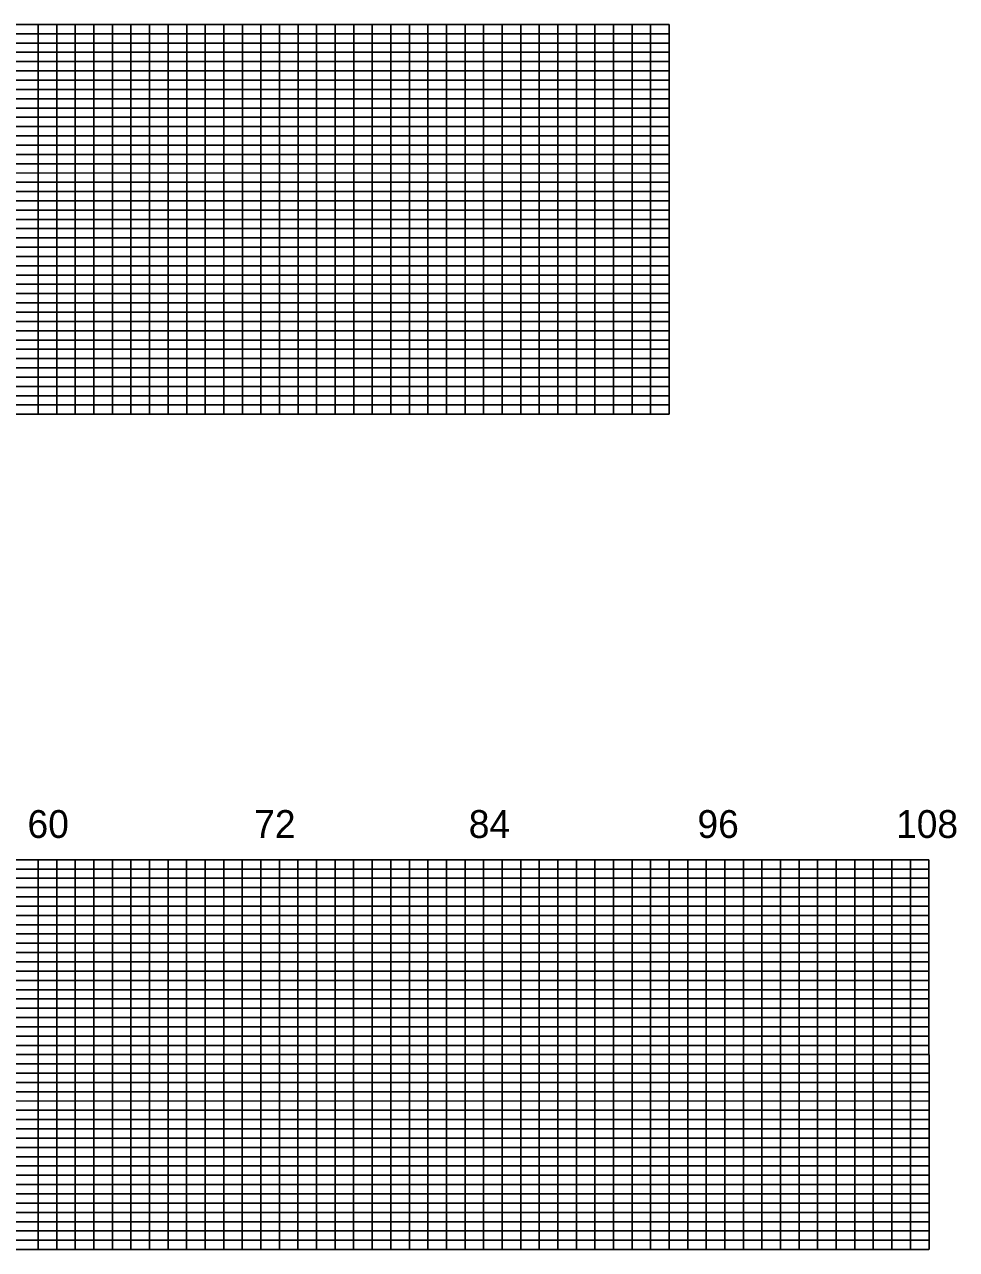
# Model space of a CAD drawing. Extents: x 1894907 to 1905782, y 740939 to 777025.
# Drawn here: x 1898545 to 1901056, y 765964 to 769264 of the extents above; entities that cross this region are included whole.
import ezdxf

# ---------------------------------------------------------------- set-up
doc = ezdxf.new("R2010")
doc.units = 0
doc.layers.add('RD_PD_WallFill', color=7, linetype='Continuous')

msp = doc.modelspace()

# ---------------------------------------------------------------- linework, layer by layer
at = {"layer": 'RD_PD_WallFill'}
for p, q in [((1894931.6, 769264.2), (1900281.6, 769264.2)), ((1895381.6, 769239.2), (1900281.6, 769239.2)), ((1898581.7, 768214.2), (1898581.7, 769264.2)), ((1898631.7, 768214.2), (1898631.7, 769264.2)), ((1898681.7, 768214.2), (1898681.7, 769264.2)), ((1898731.7, 768214.2), (1898731.7, 769264.2)), ((1898781.7, 768214.2), (1898781.7, 769264.2)), ((1898831.7, 768214.2), (1898831.7, 769264.2)), ((1898881.7, 768214.2), (1898881.7, 769264.2)), ((1898931.7, 768214.2), (1898931.7, 769264.2)), ((1898981.7, 768214.2), (1898981.7, 769264.2)), ((1899031.7, 768214.2), (1899031.7, 769264.2)), ((1899081.7, 768214.2), (1899081.7, 769264.2)), ((1899131.7, 768214.2), (1899131.7, 769264.2)), ((1899181.7, 768214.2), (1899181.7, 769264.2)), ((1899231.7, 768214.2), (1899231.7, 769264.2)), ((1899281.7, 768214.2), (1899281.7, 769264.2)), ((1899331.7, 768214.2), (1899331.7, 769264.2)), ((1899381.7, 768214.2), (1899381.7, 769264.2)), ((1899431.7, 768214.2), (1899431.7, 769264.2)), ((1899481.7, 768214.2), (1899481.7, 769264.2)), ((1899531.7, 768214.2), (1899531.7, 769264.2)), ((1899581.7, 768214.2), (1899581.7, 769264.2)), ((1899631.7, 768214.2), (1899631.7, 769264.2)), ((1899681.7, 768214.2), (1899681.7, 769264.2)), ((1899731.7, 768214.2), (1899731.7, 769264.2)), ((1899781.7, 768214.2), (1899781.7, 769264.2)), ((1899831.7, 768214.2), (1899831.7, 769264.2)), ((1899881.7, 768214.2), (1899881.7, 769264.2)), ((1899931.7, 768214.2), (1899931.7, 769264.2)), ((1899981.7, 768214.2), (1899981.7, 769264.2)), ((1900031.7, 768214.2), (1900031.7, 769264.2)), ((1900081.7, 768214.2), (1900081.7, 769264.2)), ((1900131.7, 768214.2), (1900131.7, 769264.2)), ((1900181.7, 768214.2), (1900181.7, 769264.2)), ((1900231.7, 768214.2), (1900231.7, 769264.2)), ((1900281.7, 768214.2), (1900281.7, 769264.2)), ((1895381.6, 769214.2), (1900281.6, 769214.2)), ((1895381.6, 769189.2), (1900281.6, 769189.2)), ((1895381.6, 769164.2), (1900281.6, 769164.2)), ((1895381.6, 769139.1), (1900281.6, 769139.2)), ((1894931.6, 769114.2), (1900281.6, 769114.2)), ((1894931.6, 769089.2), (1900281.6, 769089.1)), ((1894931.6, 769064.2), (1900281.6, 769064.2)), ((1894931.6, 769039.2), (1900281.6, 769039.1)), ((1894931.6, 769014.2), (1900281.6, 769014.2)), ((1894931.6, 768989.1), (1900281.6, 768989.2)), ((1894931.6, 768964.1), (1900281.6, 768964.2)), ((1894931.6, 768939.2), (1900281.6, 768939.1)), ((1894931.6, 768914.1), (1900281.6, 768914.2)), ((1894931.6, 768889.2), (1900281.6, 768889.2)), ((1894931.6, 768864.2), (1900281.6, 768864.1)), ((1894931.6, 768839.2), (1900281.6, 768839.2)), ((1894931.6, 768814.2), (1900281.6, 768814.1)), ((1894931.6, 768789.2), (1900281.6, 768789.2)), ((1894931.6, 768764.2), (1900281.6, 768764.2)), ((1894931.6, 768739.2), (1900281.6, 768739.1)), ((1894931.6, 768714.2), (1900281.6, 768714.2)), ((1894931.6, 768689.1), (1900281.6, 768689.2)), ((1894931.6, 768664.2), (1900281.6, 768664.2)), ((1894931.6, 768639.2), (1900281.6, 768639.2)), ((1894931.6, 768614.1), (1900281.6, 768614.2)), ((1894931.6, 768589.2), (1900281.6, 768589.1)), ((1894931.6, 768564.2), (1900281.6, 768564.2)), ((1894931.6, 768539.2), (1900281.6, 768539.2)), ((1894931.6, 768514.2), (1900281.6, 768514.1)), ((1894931.6, 768489.2), (1900281.6, 768489.2)), ((1894931.6, 768464.2), (1900281.6, 768464.2)), ((1894931.6, 768439.2), (1900281.6, 768439.2)), ((1894931.6, 768414.2), (1900281.6, 768414.2)), ((1894931.6, 768389.1), (1900281.6, 768389.2)), ((1894931.6, 768364.2), (1900281.6, 768364.1)), ((1894931.6, 768339.2), (1900281.6, 768339.2)), ((1894931.6, 768314.2), (1900281.6, 768314.2)), ((1894931.6, 768289.2), (1900281.6, 768289.2)), ((1894931.6, 768264.2), (1900281.6, 768264.2)), ((1894931.6, 768214.2), (1900281.6, 768214.1)), ((1894981.6, 768239.1), (1900281.6, 768239.2)), ((1895631.6, 767014.1), (1900981.6, 767014.2)), ((1898581.6, 765964.2), (1898581.6, 767014.2)), ((1898631.6, 765964.2), (1898631.6, 767014.2)), ((1898681.6, 765964.2), (1898681.6, 767014.2)), ((1898731.6, 765964.1), (1898731.6, 767014.2)), ((1898781.6, 765964.2), (1898781.6, 767014.2)), ((1898831.6, 765964.2), (1898831.6, 767014.2)), ((1898881.6, 765964.2), (1898881.6, 767014.2)), ((1898931.6, 765964.2), (1898931.6, 767014.2)), ((1898981.6, 765964.2), (1898981.6, 767014.2)), ((1899031.6, 765964.1), (1899031.6, 767014.2)), ((1899081.6, 765964.1), (1899081.6, 767014.2)), ((1899131.6, 765964.2), (1899131.6, 767014.2)), ((1899181.6, 765964.2), (1899181.6, 767014.2)), ((1899231.6, 765964.2), (1899231.6, 767014.2)), ((1899281.6, 765964.2), (1899281.6, 767014.2)), ((1899331.6, 765964.2), (1899331.6, 767014.2)), ((1899381.6, 765964.2), (1899381.6, 767014.2)), ((1899431.6, 765964.2), (1899431.6, 767014.2)), ((1899481.6, 765964.2), (1899481.6, 767014.2)), ((1899531.6, 765964.2), (1899531.6, 767014.2)), ((1899581.6, 765964.2), (1899581.6, 767014.2)), ((1899631.6, 765964.2), (1899631.6, 767014.2)), ((1899681.6, 765964.2), (1899681.6, 767014.2)), ((1899731.6, 765964.2), (1899731.6, 767014.2)), ((1899781.6, 765964.2), (1899781.6, 767014.2)), ((1899831.6, 765964.2), (1899831.6, 767014.2)), ((1899881.6, 765964.2), (1899881.6, 767014.2)), ((1899931.6, 765964.2), (1899931.6, 767014.2)), ((1899981.6, 765964.2), (1899981.6, 767014.2)), ((1900031.6, 765964.2), (1900031.6, 767014.2)), ((1900081.6, 765964.2), (1900081.6, 767014.2)), ((1900131.6, 765964.2), (1900131.6, 767014.2)), ((1900181.6, 765964.2), (1900181.6, 767014.2)), ((1900231.6, 765964.2), (1900231.6, 767014.2)), ((1900281.6, 765964.2), (1900281.6, 767014.2)), ((1900331.6, 765964.2), (1900331.6, 767014.2)), ((1900381.6, 765964.2), (1900381.6, 767014.2)), ((1900431.6, 765964.2), (1900431.6, 767014.2)), ((1900481.6, 765964.2), (1900481.6, 767014.2)), ((1900531.6, 765964.2), (1900531.6, 767014.2)), ((1900581.6, 765964.2), (1900581.6, 767014.2)), ((1900631.6, 765964.2), (1900631.6, 767014.2)), ((1900681.6, 765964.2), (1900681.6, 767014.2)), ((1900731.6, 765964.2), (1900731.6, 767014.2)), ((1900781.7, 765964.2), (1900781.6, 767014.2)), ((1900831.6, 765964.2), (1900831.7, 767014.2)), ((1900881.6, 765964.2), (1900881.6, 767014.2)), ((1900931.6, 765964.2), (1900931.6, 767014.2)), ((1900981.7, 765964.2), (1900981.6, 767014.2)), ((1896081.6, 766989.1), (1900981.6, 766989.1)), ((1896081.6, 766964.1), (1900981.6, 766964.1)), ((1896081.6, 766939.1), (1900981.6, 766939.1)), ((1896081.6, 766914.2), (1900981.6, 766914.1)), ((1895631.6, 766864.1), (1900981.6, 766864.1)), ((1896081.6, 766889.1), (1900981.6, 766889.2)), ((1895631.6, 766839.1), (1900981.6, 766839.1)), ((1895631.6, 766814.1), (1900981.6, 766814.2)), ((1895631.6, 766789.2), (1900981.6, 766789.1)), ((1895631.6, 766764.2), (1900981.6, 766764.2)), ((1895631.6, 766739.1), (1900981.6, 766739.1)), ((1895631.6, 766714.1), (1900981.6, 766714.1)), ((1895631.6, 766689.2), (1900981.6, 766689.1)), ((1895631.6, 766664.1), (1900981.6, 766664.1)), ((1895631.6, 766639.2), (1900981.6, 766639.1)), ((1895631.6, 766614.1), (1900981.6, 766614.1)), ((1895631.6, 766589.1), (1900981.6, 766589.2)), ((1895631.6, 766564.1), (1900981.6, 766564.1)), ((1895631.6, 766539.1), (1900981.6, 766539.2)), ((1895631.6, 766514.1), (1900981.6, 766514.1)), ((1895631.6, 766489.1), (1900981.6, 766489.1)), ((1895631.6, 766464.2), (1900981.6, 766464.1)), ((1895631.6, 766439.1), (1900981.6, 766439.1)), ((1895631.6, 766414.1), (1900981.6, 766414.1)), ((1895631.6, 766389.1), (1900981.6, 766389.1)), ((1895631.6, 766364.1), (1900981.6, 766364.2)), ((1895631.6, 766339.1), (1900981.6, 766339.1)), ((1895631.6, 766314.1), (1900981.6, 766314.1)), ((1895631.6, 766289.1), (1900981.6, 766289.1)), ((1895631.6, 766264.1), (1900981.6, 766264.1)), ((1895631.6, 766239.1), (1900981.6, 766239.1)), ((1895631.6, 766214.1), (1900981.6, 766214.1)), ((1895631.6, 766189.1), (1900981.6, 766189.1)), ((1895631.6, 766164.1), (1900981.6, 766164.1)), ((1895631.6, 766139.1), (1900981.6, 766139.1)), ((1895631.6, 766114.1), (1900981.6, 766114.1)), ((1895631.6, 766089.1), (1900981.6, 766089.1)), ((1895631.6, 766064.1), (1900981.6, 766064.1)), ((1895631.6, 766039.1), (1900981.6, 766039.1)), ((1895631.6, 766014.1), (1900981.6, 766014.1)), ((1895681.6, 765989.1), (1900981.6, 765989.1)), ((1895631.6, 765964.1), (1900981.6, 765964.1))]:
    msp.add_line(p, q, dxfattribs=at)

# ---------------------------------------------------------------- texts
for s, p in [('60', (1898552.8, 767072.8)), ('72', (1899163.5, 767072.8)), ('84', (1899741.7, 767072.8)), ('96', (1900357.8, 767072.8)), ('108', (1900892.8, 767072.8))]:
    msp.add_text(s, height=75, dxfattribs=at).set_placement(p)

doc.saveas('drawing.dxf')
